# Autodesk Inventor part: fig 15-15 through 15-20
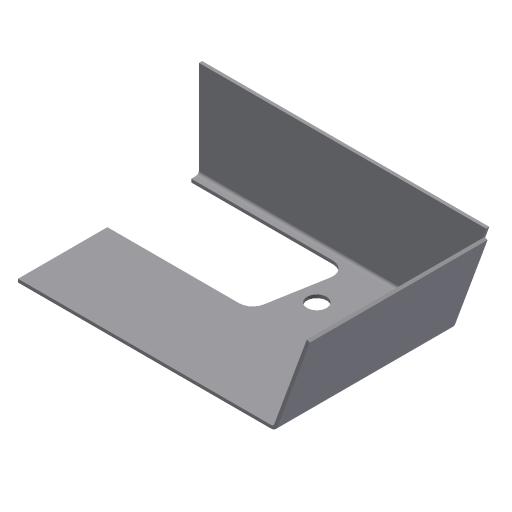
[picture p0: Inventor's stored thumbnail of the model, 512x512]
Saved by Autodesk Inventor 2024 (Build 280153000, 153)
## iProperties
Created: 2005-03
Part Number: fig 15-15 through 15-20
Document SubType Name: Sheet Metal
Designer: CADCIM
Manufacturer: Standard
Standards Organization: Custom
Density: 1 g/cm^3
Sheet Metal Rule: Default
Material: Generic
Flat Pattern Width: 4.32624 cm
Flat Pattern Length: 5.50678 cm
Flat Pattern Area: 23.8236 cm^2
Sheet Metal Width: 43.262 mm
Sheet Metal Length: 55.068 mm
Sheet Metal Area: 2382.364 mm^2
Appearance: Default
Author: CADCIM
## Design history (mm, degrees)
node "Face2"
  sketch "Sketch1" dims "d32" = 0.5 (= BendRadius), "CornerReliefSize" = 2 (= 4 x Thickness)
    geometry: L1 (-36, -8.631)-(4.238, -8.631); L2 (4.238, -8.631)-(4.238, 20); L3 (4.238, 20)-(-36, 20); L4 (-36, 20)-(-36, -8.631)
    constraints: 8 end point, 2 parallel, 1 horizontal, 1 perpendicular
node "Flange3"
node "Flange2"
feature "Corner2" dims "d36" = 2 (= CornerReliefSize), "d37" = 0.5 (= BendRadius), "d38" = 0.5 (= Thickness), "d39" = 0, "d49" = 0.5 (= Thickness)
sketch "Sketch6"
  geometry: 3 further points
feature "iFeature14:1" sketch "Sketch6" dims "d43" = 3.048 (derived), "d45" = 16.6624 (derived)
body "Solid1"
sketch "Sketch5"
  geometry: 1 further point
face "Plate2" dims "d49" = 0.5 (= Thickness), "CornerReliefSize" = 2 (= 4 x Thickness)
sketch "Sketch3" dims "BendReliefDepth" = 0.25 (= 0.5 x Thickness)
  geometry: L1 (39.356, 0)-(39.356, 15); L2 (39.356, 15)-(0, 15); 1 other entity
  constraints: 4 end point, 4 other
face "Plate4" dims "d18" = 0.5 (= BendReliefWidth), "d20" = 1 (= MinimumRemnant), "d22" = 15, "d23" = 90 deg, "d24" = 0.5 (= BendRadius), "d32" = 0.5 (= BendRadius), "d49" = 0.5 (= Thickness), "BendReliefDepth" = 0.25 (= 0.5 x Thickness), "CornerReliefSize" = 2 (= 4 x Thickness)
bend "Bend2" dims "d18" = 0.5 (= BendReliefWidth), "d19" = 0.25 (= BendReliefDepth), "d20" = 1 (= MinimumRemnant), "d21" = 0.5 (= BendRadius), "d22" = 15, "d23" = 90 deg, "d24" = 0.5 (= BendRadius), "d49" = 0.5 (= Thickness), "SeamGap" = 0.01
node "FlatPattern"
sketch "Sketch4" dims "d32" = 0.5 (= BendRadius)
  geometry: L1 (28.631, 0)-(28.631, 15); L2 (28.631, 15)-(0, 15); 1 other entity
  constraints: 4 end point, 4 other
face "Plate5" dims "d29" = 0.5 (= BendReliefWidth), "d31" = 1 (= MinimumRemnant), "d32" = 0.5 (= BendRadius), "d33" = 15, "d34" = 70 deg, "d35" = 0.5 (= BendRadius), "d49" = 0.5 (= Thickness), "CornerReliefSize" = 2 (= 4 x Thickness)
bend "Bend3" dims "d29" = 0.5 (= BendReliefWidth), "d30" = 0.25 (= BendReliefDepth), "d31" = 1 (= MinimumRemnant), "d32" = 0.5 (= BendRadius), "d33" = 15, "d34" = 70 deg, "d35" = 0.5 (= BendRadius), "d49" = 0.5 (= Thickness), "SeamGap" = 0.01
feature "FlatPatternExtrusion2" dims "d0" = 0.5 (derived)
other parameters: "Thickness" = 0.5, "BendRadius" = 0.5 (= Thickness), "BendReliefWidth" = 0.5 (= Thickness), "MinimumRemnant" = 1 (= 2 x Thickness), "TransitionRadius" = 0.5 (= BendRadius), "d0" = 0.5 (= BendRadius), "d10" = 0.5 (= BendRadius), "JacobiRadiusSize" = 0.5 (= Thickness), "GapSize" = 0.5 (= Thickness), "d48" = 0
